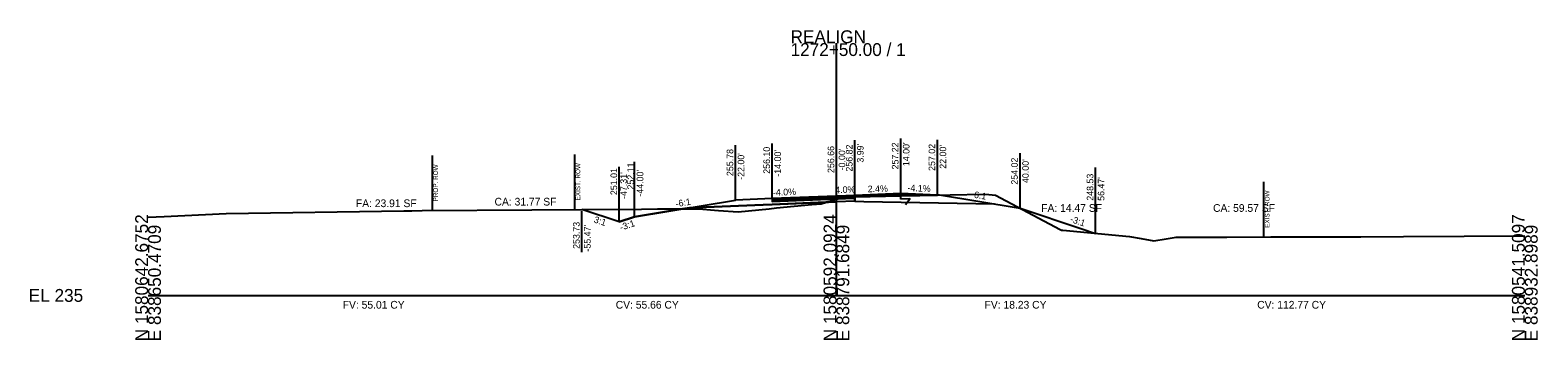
# Model space of a CAD drawing. Extents: x -26 to 6303, y -16 to 9563.
# Drawn here: x 4974.3 to 5302.8, y 5990.3 to 6057.8 of the extents above; entities that cross this region are included whole.
import ezdxf

# ---------------------------------------------------------------- set-up
doc = ezdxf.new("R2010")
doc.units = 0
for name, color, linetype in [('ASPHALT_19MM1', 7, 'Continuous'), ('ASPHALT_9_5MM1', 7, 'Continuous'), ('CONST_DCH', 7, 'Continuous'), ('CONST_LV3', 7, 'Continuous'), ('Default', 7, 'Continuous'), ('Draft_XS_Grid', 7, 'Continuous'), ('DTM_TEMP_DROP', 7, 'Continuous'), ('DTM_X_GROUND', 7, 'Continuous'), ('X_TRANS_EOP', 7, 'Continuous'), ('XS_CELL', 7, 'Continuous'), ('XS_M_SHAPES_EARTHWORK', 7, 'Continuous'), ('XS_P_ASPHALT', 7, 'Continuous'), ('XS_P_GROUND', 7, 'Continuous'), ('XS_P_ROW', 7, 'Continuous'), ('XS_P_SHOULDER', 7, 'Continuous'), ('XS_P_SUBGRADE_GRANULAR', 7, 'Continuous'), ('XS_P_SUBGRADE_LEVELING', 7, 'Continuous'), ('XS_P_SUBGRADE_MILLING', 7, 'Continuous'), ('XS_P_TX_CLEARZONE', 7, 'Continuous'), ('XS_P_TX_FS_BS', 7, 'Continuous'), ('XS_SHEET_EW_TX_AREA', 7, 'Continuous'), ('XS_SHEET_EW_TX_VOLUME', 7, 'Continuous'), ('XS_X_ROW', 7, 'Continuous')]:
    doc.layers.add(name, color=color, linetype=linetype)

msp = doc.modelspace()

# ---------------------------------------------------------------- linework, layer by layer
at = {"layer": 'ASPHALT_19MM1'}
msp.add_lwpolyline([(5136, 6020.77), (5136, 6020.5), (5150, 6021.06), (5150, 6021.06), (5150, 6021.06), (5153.99, 6021.22), (5153.99, 6021.22), (5153.99, 6021.49), (5150, 6021.33), (5150, 6021.33), (5150, 6021.33), (5136, 6020.77), (5136, 6020.77)], dxfattribs=at)
at = {"layer": 'ASPHALT_9_5MM1'}
msp.add_lwpolyline([(5136, 6021.1), (5136, 6020.98), (5150, 6021.54), (5150, 6021.54), (5150, 6021.54), (5153.99, 6021.7), (5153.99, 6021.7), (5153.99, 6021.82), (5150, 6021.66), (5150, 6021.66), (5150, 6021.66), (5136, 6021.1), (5136, 6021.1)], dxfattribs=at)
at = {"layer": 'CONST_LV3'}
for points in [[(5153.99, 6021.82), (5150, 6021.66), (5150, 6021.66)], [(5172, 6021.89), (5153.99, 6021.82), (5153.99, 6021.82)]]:
    msp.add_lwpolyline(points, dxfattribs=at)
at = {"layer": 'Default'}
msp.add_lwpolyline([(5136, 6020.98), (5136, 6020.77), (5150, 6021.33), (5150, 6021.33), (5150, 6021.33), (5153.99, 6021.49), (5153.99, 6021.49), (5153.99, 6021.7), (5150, 6021.54), (5150, 6021.54), (5150, 6021.54), (5136, 6020.98), (5136, 6020.98)], dxfattribs=at)
at = {"layer": 'DTM_X_GROUND'}
msp.add_lwpolyline([(5000, 6017.06), (5003.52, 6017.23), (5016.99, 6017.84), (5055.76, 6018.44), (5057.5, 6018.47), (5059.72, 6018.49), (5107.53, 6018.82), (5111.01, 6018.85), (5113.5, 6018.85), (5120.03, 6018.87), (5124.33, 6018.53), (5128.58, 6018.19), (5135.36, 6018.91), (5136.97, 6019.09), (5144.63, 6019.81), (5146.67, 6020), (5147.65, 6020.29), (5150.81, 6021.22), (5153.33, 6021.47), (5153.99, 6021.53), (5164.78, 6021.75), (5168.19, 6021.82), (5174.78, 6021.95), (5182.14, 6022.09), (5183.18, 6021.99), (5184.64, 6021.85), (5198.76, 6014.4), (5199.06, 6014.24), (5199.3, 6014.21), (5213.89, 6012.81), (5216.38, 6012.4), (5219.15, 6011.92), (5221.83, 6012.34), (5224.02, 6012.69), (5235.06, 6012.72), (5244.65, 6012.75), (5249.46, 6012.76), (5264.29, 6012.77), (5273.6, 6012.84), (5300, 6012.96)], dxfattribs=at)
at = {"layer": 'XS_CELL'}
for p, q in [((5150, 6000), (5150, 6055)), ((5000, 6000), (5150, 6000)), ((5150, 6000), (5300, 6000))]:
    msp.add_line(p, q, dxfattribs=at)
at = {"layer": 'XS_M_SHAPES_EARTHWORK'}
for points in [[(5164, 6021.74), (5164.78, 6021.75), (5168.19, 6021.82), (5171.99, 6021.89), (5164, 6022.22), (5164, 6022.1)], [(5094.53, 6018.73), (5107.53, 6018.82), (5111.01, 6018.85), (5113.5, 6018.85), (5116.48, 6018.86), (5106, 6017.11), (5102.69, 6016.01)], [(5116.48, 6018.86), (5120.03, 6018.87), (5124.33, 6018.53), (5128.58, 6018.19), (5135.36, 6018.91), (5136.97, 6019.09), (5144.63, 6019.81), (5146.67, 6020), (5147.65, 6020.29), (5147.67, 6020.3), (5136, 6019.83), (5134, 6019.75), (5117.97, 6019.11)], [(5147.67, 6020.3), (5150.81, 6021.22), (5153.33, 6021.47), (5153.99, 6021.53), (5153.99, 6021.49), (5153.99, 6021.22), (5153.99, 6020.55), (5150, 6020.39)]]:
    msp.add_lwpolyline(points, close=True, dxfattribs=at)
at = {"layer": 'XS_P_ASPHALT'}
msp.add_lwpolyline([(5153.99, 6021.82), (5153.99, 6021.7), (5164, 6022.1), (5164, 6022.22), (5153.99, 6021.82)], dxfattribs=at)
at = {"layer": 'XS_P_GROUND'}
for points in [[(5172, 6022.02), (5190, 6019.02), (5203.5, 6014.52), (5206.47, 6013.53)], [(5102.69, 6016.01), (5094.53, 6018.73)], [(5102.69, 6016.01), (5106, 6017.11), (5106, 6017.11), (5128, 6020.78), (5128, 6020.78)], [(5172, 6021.89), (5172, 6021.89)]]:
    msp.add_lwpolyline(points, dxfattribs=at)
at = {"layer": 'XS_P_ROW'}
msp.add_line((5061.96, 6018.5), (5061.96, 6030.5), dxfattribs=at)
at = {"layer": 'XS_P_SHOULDER'}
for points in [[(5172, 6021.89), (5164, 6022.22), (5164, 6022.22)], [(5136, 6021.1), (5128, 6020.78)]]:
    msp.add_lwpolyline(points, dxfattribs=at)
at = {"layer": 'XS_P_SUBGRADE_GRANULAR'}
for points in [[(5164, 6020.95), (5164, 6022.1)], [(5117.97, 6019.11), (5134, 6019.75), (5134, 6019.75), (5136, 6019.83), (5136, 6019.83)], [(5136, 6019.83), (5150, 6020.39), (5150, 6020.39)], [(5153.99, 6020.55), (5150, 6020.39), (5150, 6020.39)], [(5153.99, 6020.55), (5153.99, 6021.82)], [(5153.99, 6020.55), (5155.99, 6020.51), (5184.45, 6019.94)], [(5165.07, 6019.84), (5166, 6021.03), (5166, 6021.03), (5166, 6021.03), (5164, 6020.95)]]:
    msp.add_lwpolyline(points, dxfattribs=at)
at = {"layer": 'XS_P_SUBGRADE_LEVELING'}
msp.add_lwpolyline([(5164, 6022.1), (5153.99, 6021.7), (5153.99, 6021.7), (5153.99, 6021.7), (5153.99, 6021.53), (5153.99, 6021.53), (5153.99, 6021.53), (5164, 6021.74), (5164, 6021.74), (5164, 6022.1), (5164, 6022.1)], dxfattribs=at)
at = {"layer": 'XS_P_SUBGRADE_MILLING'}
msp.add_lwpolyline([(5164, 6021.74), (5164, 6021.74), (5153.99, 6021.53), (5153.99, 6021.53), (5153.99, 6021.53)], dxfattribs=at)
msp.add_lwpolyline([(5164, 6021.74), (5164, 6021.74), (5153.99, 6021.53), (5153.99, 6021.53), (5153.99, 6021.53)], dxfattribs=at)
at = {"layer": 'XS_P_TX_CLEARZONE'}
for p, q in [((5128, 6020.78), (5128, 6032.78)), ((5136, 6021.1), (5136, 6033.1)), ((5150, 6021.66), (5150, 6033.66)), ((5153.99, 6021.82), (5153.99, 6033.82)), ((5164, 6022.22), (5164, 6034.22)), ((5172, 6021.89), (5172, 6033.89)), ((5172, 6021.89), (5172, 6033.89)), ((5106, 6017.11), (5106, 6029.11)), ((5190, 6019.02), (5190, 6031.02)), ((5102.69, 6016.01), (5102.69, 6028.01)), ((5206.47, 6013.53), (5206.47, 6027.89)), ((5094.53, 6009.45), (5094.53, 6018.4))]:
    msp.add_line(p, q, dxfattribs=at)
at = {"layer": 'XS_X_ROW'}
for p, q in [((5092.97, 6018.72), (5092.97, 6030.72)), ((5243.16, 6012.75), (5243.16, 6024.75))]:
    msp.add_line(p, q, dxfattribs=at)

# ---------------------------------------------------------------- texts
at = {"layer": 'CONST_DCH'}
for p in [(5171.92, 6021.9), (5189.92, 6018.9)]:
    msp.add_text('X', height=0.24, dxfattribs=at).set_placement(p)
at = {"layer": 'Draft_XS_Grid'}
msp.add_text('-', height=0.0001, dxfattribs=at).set_placement((5000, 6000))
at = {"layer": 'DTM_TEMP_DROP'}
for p in [(5163.92, 6022.1), (5135.92, 6020.98), (5149.92, 6021.54), (5153.91, 6021.7)]:
    msp.add_text('X', height=0.24, dxfattribs=at).set_placement(p)
at = {"layer": 'X_TRANS_EOP'}
for p in [(5171.92, 6021.77), (5094.45, 6018.61)]:
    msp.add_text('X', height=0.24, dxfattribs=at).set_placement(p)
at = {"layer": 'XS_CELL'}
for s, p in [('1272+50.00 / 1', (5140, 6052.2)), ('REALIGN', (5140, 6055)), ('EL 235', (4974, 5998.6))]:
    msp.add_text(s, height=2.8, dxfattribs=at).set_placement(p)
for s, p in [('N 1580642.6752', (5000, 5990)), ('N 1580592.0924', (5150, 5990)), ('N 1580541.5097', (5300, 5990)), ('E 838650.4709', (5002.8, 5990)), ('E 838791.6849', (5152.8, 5990)), ('E 838932.8989', (5302.8, 5990))]:
    msp.add_text(s, height=2.8, rotation=90, dxfattribs=at).set_placement(p)
at = {"layer": 'XS_P_ASPHALT'}
msp.add_text('X', height=0.24, dxfattribs=at).set_placement((5105.92, 6016.99))
at = {"layer": 'XS_P_GROUND'}
msp.add_text('X', height=0.24, dxfattribs=at).set_placement((5171.92, 6021.77))
at = {"layer": 'XS_P_ROW'}
msp.add_text('PROP. ROW', height=1, rotation=90, dxfattribs=at).set_placement((5063.16, 6020.5))
at = {"layer": 'XS_P_SHOULDER'}
for p in [(5171.92, 6021.77), (5127.92, 6020.66), (5206.39, 6013.41)]:
    msp.add_text('X', height=0.24, dxfattribs=at).set_placement(p)
at = {"layer": 'XS_P_SUBGRADE_GRANULAR'}
for p in [(5171.92, 6021.77), (5102.61, 6015.89), (5206.39, 6013.41)]:
    msp.add_text('X', height=0.24, dxfattribs=at).set_placement(p)
at = {"layer": 'XS_P_TX_CLEARZONE'}
for s, p in [('256.10', (5135.52, 6026.52)), ('256.66', (5149.52, 6026.69)), ("-0.00'", (5151.92, 6027.27)), ('256.82', (5153.51, 6027)), ("3.99'", (5155.91, 6028.95)), ('257.22', (5163.52, 6027.47)), ("14.00'", (5165.92, 6028.19)), ('257.02', (5171.52, 6027.15)), ("22.00'", (5173.92, 6027.62)), ('252.11', (5105.87, 6023.09)), ('255.78', (5127.52, 6026.03)), ("-22.00'", (5129.92, 6025.21)), ("-14.00'", (5137.92, 6025.89)), ('254.02', (5189.52, 6024.15)), ("40.00'", (5191.92, 6024.51)), ('251.01', (5102.21, 6021.87)), ("-47.31'", (5104.34, 6021.03)), ("-44.00'", (5107.92, 6021.54)), ('248.53', (5205.99, 6020.65)), ("56.47'", (5208.39, 6020.62)), ('253.73', (5094.05, 6010.15)), ("-55.47'", (5096.45, 6009.56))]:
    msp.add_text(s, height=1.44, rotation=90, dxfattribs=at).set_placement(p)
at = {"layer": 'XS_P_TX_FS_BS'}
for s, rotation, p in [('-4.0%', 2.2906, (5136.18, 6021.71)), ('4.0%', 2.2906, (5149.77, 6022.25)), ('2.4%', 1.3499, (5156.83, 6022.49)), ('-4.1%', 357.6563, (5165.47, 6022.76)), ('-6:1', 350.5377, (5179.28, 6021.41)), ('-6:1', 9.4642, (5115.08, 6019.24)), ('3:1', 341.5651, (5097.01, 6015.95)), ('-3:1', 18.4332, (5103.08, 6014.1)), ('-3:1', 341.5651, (5200.8, 6016.05))]:
    msp.add_text(s, height=1.44, rotation=rotation, dxfattribs=at).set_placement(p)
at = {"layer": 'XS_SHEET_EW_TX_AREA'}
for s, p in [('FA: 23.91 SF', (5045.29, 6019.25)), ('CA: 31.77 SF', (5075.5, 6019.6)), ('FA: 14.47 SF', (5194.62, 6018.22)), ('CA: 59.57 SF', (5232.07, 6018.22))]:
    msp.add_text(s, height=1.68, dxfattribs=at).set_placement(p)
at = {"layer": 'XS_SHEET_EW_TX_VOLUME'}
for s, p in [('FV: 55.01 CY', (5042.42, 5997.12)), ('CV: 55.66 CY', (5101.91, 5997.12)), ('FV: 18.23 CY', (5182.28, 5997.12)), ('CV: 112.77 CY', (5241.69, 5997.12))]:
    msp.add_text(s, height=1.68, dxfattribs=at).set_placement(p)
at = {"layer": 'XS_X_ROW'}
for p in [(5094.17, 6020.72), (5244.36, 6014.75)]:
    msp.add_text('EXIST. ROW', height=1, rotation=90, dxfattribs=at).set_placement(p)

doc.saveas('drawing.dxf')
